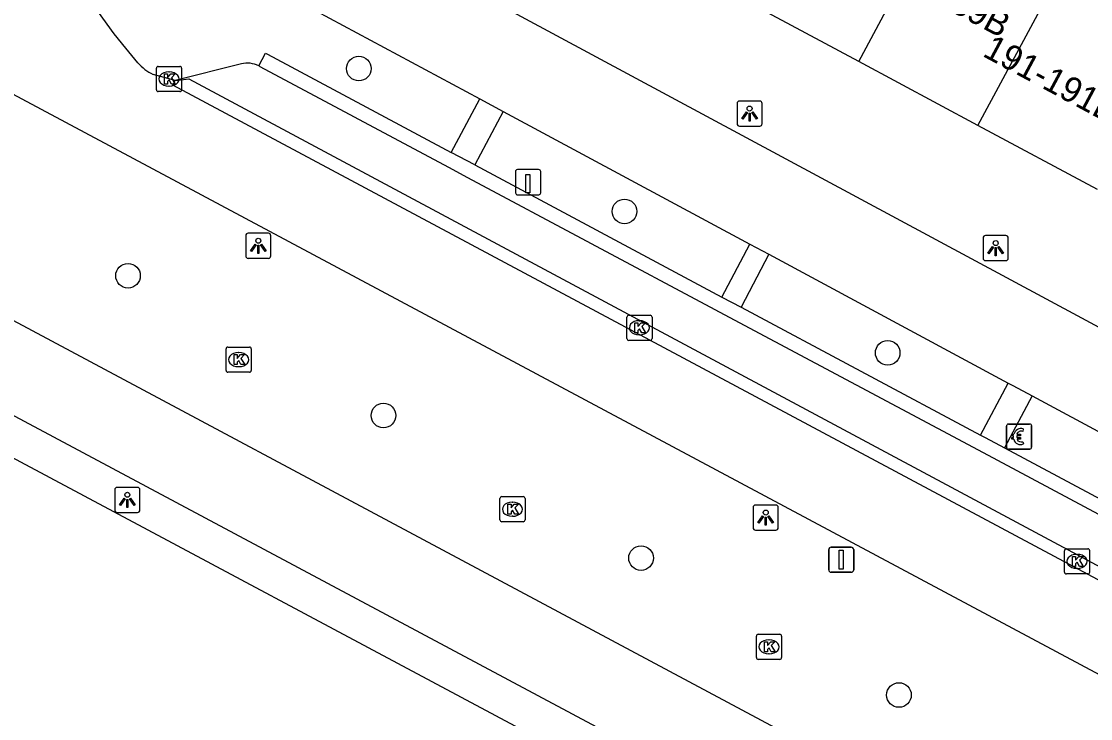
# Model space of a CAD drawing. Extents: x 159489 to 160304, y 383826 to 384530.
# Drawn here: x 159726.37 to 159768.87, y 384018.26 to 384045.99 of the extents above; entities that cross this region are included whole.
import ezdxf

# ---------------------------------------------------------------- set-up
doc = ezdxf.new("R2010")
doc.units = 0
for name, color, linetype in [('IMGEO_Betaalautomaat', 7, 'Continuous'), ('IMGEO_Boom', 7, 'Continuous'), ('IMGEO_Fietspad_gesloten', 7, 'Continuous'), ('IMGEO_Kolk', 7, 'Continuous'), ('IMGEO_Laadpaal', 7, 'Continuous'), ('IMGEO_Lichtpunt', 7, 'Continuous'), ('IMGEO_OVBaan_gesloten', 7, 'Continuous'), ('IMGEO_Pand', 7, 'Continuous'), ('IMGEO_Pand_nummerreeks', 7, 'Continuous'), ('IMGEO_Parkeervlak_open', 7, 'Continuous'), ('IMGEO_Rijbaan_lokaal_gesloten', 7, 'Continuous'), ('IMGEO_Rijbaan_lokaal_open', 7, 'Continuous'), ('IMGEO_Verkeersbordpaal', 7, 'Continuous'), ('IMGEO_Voetpad_open', 7, 'Continuous')]:
    doc.layers.add(name, color=color, linetype=linetype)

msp = doc.modelspace()

# ---------------------------------------------------------------- linework, layer by layer
at = {"layer": 'IMGEO_Betaalautomaat'}
for p, q in [((159765.601, 384029.975), (159766.442, 384029.975)), ((159766.442, 384029.975), (159765.601, 384029.975)), ((159765.526, 384029.051), (159765.526, 384029.892)), ((159765.526, 384029.892), (159765.526, 384029.051)), ((159765.809, 384029.439), (159765.809, 384029.507)), ((159765.93, 384029.507), (159765.93, 384029.439)), ((159766.188, 384029.78), (159766.171, 384029.68)), ((159766.525, 384029.901), (159766.525, 384029.06)), ((159766.525, 384029.06), (159766.525, 384029.901)), ((159766.175, 384029.274), (159766.197, 384029.187)), ((159766.451, 384028.976), (159765.61, 384028.976)), ((159765.61, 384028.976), (159766.451, 384028.976))]:
    msp.add_line(p, q, dxfattribs=at)
for points in [[(159765.809, 384029.507), (159765.74, 384029.507), (159765.74, 384029.576), (159765.819, 384029.576)], [(159765.941, 384029.576), (159766.088, 384029.576), (159766.088, 384029.507), (159765.93, 384029.507)], [(159765.814, 384029.37), (159765.74, 384029.37), (159765.74, 384029.439), (159765.809, 384029.439)], [(159765.93, 384029.439), (159766.088, 384029.439), (159766.088, 384029.37), (159765.944, 384029.37)]]:
    msp.add_lwpolyline(points, dxfattribs=at)
for centre, radius, start, end in [((159765.604, 384029.898), 0.0779, 92.4484, 184.2845), ((159765.604, 384029.898), 0.0779, 92.4484, 184.2845), ((159766.448, 384029.898), 0.0779, 2.4484, 94.2845), ((159766.448, 384029.898), 0.0779, 2.4484, 94.2845), ((159766.102, 384029.5), 0.293, 73.014, 165.0139), ((159766.108, 384029.513), 0.179, 69.3236, 159.5683), ((159766.075, 384029.425), 0.267, 191.8096, 297.0389), ((159766.108, 384029.44), 0.179, 202.7625, 291.8693), ((159765.604, 384029.054), 0.0779, 182.4484, 274.2845), ((159765.604, 384029.054), 0.0779, 182.4484, 274.2845), ((159766.448, 384029.054), 0.0779, 272.4484, 4.2845), ((159766.448, 384029.054), 0.0779, 272.4484, 4.2845)]:
    msp.add_arc(centre, radius, start, end, dxfattribs=at)
at = {"layer": 'IMGEO_Boom'}
for centre in [(159739.784, 384044.112), (159750.343, 384038.433), (159730.609, 384035.874), (159760.803, 384032.807), (159740.762, 384030.315), (159751, 384024.645), (159761.251, 384019.198)]:
    msp.add_circle(centre, 0.489, dxfattribs=at)
at = {"layer": 'IMGEO_Fietspad_gesloten'}
for points in [[(159797.098, 384018.803), (159731.166, 384054.292)], [(159729.77, 384050.977), (159731.079, 384050.354), (159731.013, 384050.208), (159744.588, 384042.906)], [(159744.588, 384042.906), (159745.526, 384042.402)], [(159745.526, 384042.402), (159755.319, 384037.135)], [(159755.319, 384037.135), (159756.08, 384036.725)], [(159756.08, 384036.725), (159765.597, 384031.607)], [(159765.597, 384031.607), (159765.779, 384031.509), (159766.543, 384031.098)], [(159766.543, 384031.098), (159776.103, 384025.957), (159776.158, 384025.928)]]:
    msp.add_lwpolyline(points, dxfattribs=at)
at = {"layer": 'IMGEO_Kolk'}
for p, q in [((159731.739, 384043.272), (159731.739, 384044.124)), ((159731.814, 384044.198), (159732.666, 384044.198)), ((159732.227, 384043.978), (159732.252, 384043.978)), ((159732.74, 384044.124), (159732.74, 384043.272)), ((159732.666, 384043.198), (159731.814, 384043.198)), ((159732.25, 384043.418), (159732.225, 384043.418)), ((159750.435, 384033.378), (159750.435, 384034.23)), ((159750.51, 384034.304), (159751.362, 384034.304)), ((159751.436, 384034.23), (159751.436, 384033.378)), ((159750.923, 384034.084), (159750.948, 384034.084)), ((159750.946, 384033.524), (159750.921, 384033.524)), ((159734.506, 384032.111), (159734.506, 384032.963)), ((159734.581, 384033.037), (159735.433, 384033.037)), ((159735.507, 384032.963), (159735.507, 384032.111)), ((159751.362, 384033.304), (159750.51, 384033.304)), ((159734.994, 384032.817), (159735.019, 384032.817)), ((159735.017, 384032.257), (159734.992, 384032.257)), ((159735.433, 384032.037), (159734.581, 384032.037)), ((159745.388, 384026.162), (159745.388, 384027.014)), ((159745.463, 384027.088), (159746.315, 384027.088)), ((159746.389, 384027.014), (159746.389, 384026.162)), ((159745.876, 384026.868), (159745.901, 384026.868)), ((159745.899, 384026.308), (159745.874, 384026.308)), ((159746.315, 384026.088), (159745.463, 384026.088)), ((159767.83, 384024.087), (159767.83, 384024.939)), ((159767.905, 384025.013), (159768.757, 384025.013)), ((159768.831, 384024.939), (159768.831, 384024.087)), ((159768.318, 384024.793), (159768.343, 384024.793)), ((159768.757, 384024.013), (159767.905, 384024.013)), ((159768.341, 384024.233), (159768.316, 384024.233)), ((159755.585, 384020.689), (159755.585, 384021.541)), ((159755.66, 384021.615), (159756.512, 384021.615)), ((159756.586, 384021.541), (159756.586, 384020.689)), ((159756.073, 384021.395), (159756.098, 384021.395)), ((159756.512, 384020.615), (159755.66, 384020.615)), ((159756.096, 384020.835), (159756.071, 384020.835))]:
    msp.add_line(p, q, dxfattribs=at)
for points in [[(159731.739, 384043.272), (159731.739, 384044.124)], [(159731.814, 384044.198), (159732.666, 384044.198)], [(159732.74, 384044.124), (159732.74, 384043.272)], [(159732.06, 384043.898), (159732.183, 384043.898), (159732.183, 384043.747), (159732.313, 384043.898), (159732.477, 384043.898), (159732.331, 384043.747), (159732.484, 384043.498), (159732.332, 384043.498), (159732.247, 384043.662), (159732.183, 384043.595), (159732.183, 384043.498), (159732.06, 384043.498), (159732.06, 384043.898)], [(159732.666, 384043.198), (159731.814, 384043.198)], [(159750.435, 384033.378), (159750.435, 384034.23)], [(159750.51, 384034.304), (159751.362, 384034.304)], [(159751.436, 384034.23), (159751.436, 384033.378)], [(159750.756, 384034.004), (159750.879, 384034.004), (159750.879, 384033.853), (159751.009, 384034.004), (159751.173, 384034.004), (159751.027, 384033.853), (159751.18, 384033.604), (159751.028, 384033.604), (159750.943, 384033.768), (159750.879, 384033.701), (159750.879, 384033.604), (159750.756, 384033.604), (159750.756, 384034.004)], [(159734.506, 384032.111), (159734.506, 384032.963)], [(159734.581, 384033.037), (159735.433, 384033.037)], [(159735.507, 384032.963), (159735.507, 384032.111)], [(159751.362, 384033.304), (159750.51, 384033.304)], [(159734.827, 384032.737), (159734.95, 384032.737), (159734.95, 384032.586), (159735.08, 384032.737), (159735.244, 384032.737), (159735.098, 384032.586), (159735.251, 384032.337), (159735.099, 384032.337), (159735.014, 384032.501), (159734.95, 384032.434), (159734.95, 384032.337), (159734.827, 384032.337), (159734.827, 384032.737)], [(159735.433, 384032.037), (159734.581, 384032.037)], [(159745.388, 384026.162), (159745.388, 384027.014)], [(159745.463, 384027.088), (159746.315, 384027.088)], [(159746.389, 384027.014), (159746.389, 384026.162)], [(159745.709, 384026.788), (159745.832, 384026.788), (159745.832, 384026.637), (159745.962, 384026.788), (159746.126, 384026.788), (159745.98, 384026.637), (159746.133, 384026.388), (159745.981, 384026.388), (159745.896, 384026.552), (159745.832, 384026.485), (159745.832, 384026.388), (159745.709, 384026.388), (159745.709, 384026.788)], [(159746.315, 384026.088), (159745.463, 384026.088)], [(159767.83, 384024.087), (159767.83, 384024.939)], [(159767.905, 384025.013), (159768.757, 384025.013)], [(159768.831, 384024.939), (159768.831, 384024.087)], [(159768.151, 384024.713), (159768.274, 384024.713), (159768.274, 384024.562), (159768.404, 384024.713), (159768.568, 384024.713), (159768.422, 384024.562), (159768.575, 384024.313), (159768.423, 384024.313), (159768.338, 384024.477), (159768.274, 384024.41), (159768.274, 384024.313), (159768.151, 384024.313), (159768.151, 384024.713)], [(159768.757, 384024.013), (159767.905, 384024.013)], [(159755.585, 384020.689), (159755.585, 384021.541)], [(159755.66, 384021.615), (159756.512, 384021.615)], [(159756.586, 384021.541), (159756.586, 384020.689)], [(159755.906, 384021.315), (159756.029, 384021.315), (159756.029, 384021.164), (159756.159, 384021.315), (159756.323, 384021.315), (159756.177, 384021.164), (159756.33, 384020.915), (159756.178, 384020.915), (159756.093, 384021.079), (159756.029, 384021.012), (159756.029, 384020.915), (159755.906, 384020.915), (159755.906, 384021.315)], [(159756.512, 384020.615), (159755.66, 384020.615)]]:
    msp.add_lwpolyline(points, dxfattribs=at)
for centre, start, end in [((159731.816, 384044.122), 91.552, 178.448), ((159731.816, 384044.122), 91.552, 178.448), ((159732.664, 384044.122), 1.552, 88.448), ((159732.664, 384044.122), 1.552, 88.448), ((159731.816, 384043.274), 181.552, 268.448), ((159731.816, 384043.274), 181.552, 268.448), ((159732.664, 384043.274), 271.552, 358.448), ((159732.664, 384043.274), 271.552, 358.448), ((159750.512, 384034.228), 91.552, 178.448), ((159750.512, 384034.228), 91.552, 178.448), ((159751.36, 384034.228), 1.552, 88.448), ((159751.36, 384034.228), 1.552, 88.448), ((159750.512, 384033.38), 181.552, 268.448), ((159750.512, 384033.38), 181.552, 268.448), ((159751.36, 384033.38), 271.552, 358.448), ((159751.36, 384033.38), 271.552, 358.448), ((159734.583, 384032.961), 91.552, 178.448), ((159734.583, 384032.961), 91.552, 178.448), ((159735.431, 384032.961), 1.552, 88.448), ((159735.431, 384032.961), 1.552, 88.448), ((159734.583, 384032.113), 181.552, 268.448), ((159734.583, 384032.113), 181.552, 268.448), ((159735.431, 384032.113), 271.552, 358.448), ((159735.431, 384032.113), 271.552, 358.448), ((159745.465, 384027.012), 91.552, 178.448), ((159745.465, 384027.012), 91.552, 178.448), ((159746.313, 384027.012), 1.552, 88.448), ((159746.313, 384027.012), 1.552, 88.448), ((159745.465, 384026.164), 181.552, 268.448), ((159745.465, 384026.164), 181.552, 268.448), ((159746.313, 384026.164), 271.552, 358.448), ((159746.313, 384026.164), 271.552, 358.448), ((159767.907, 384024.937), 91.552, 178.448), ((159767.907, 384024.937), 91.552, 178.448), ((159768.755, 384024.937), 1.552, 88.448), ((159768.755, 384024.937), 1.552, 88.448), ((159767.907, 384024.089), 181.552, 268.448), ((159767.907, 384024.089), 181.552, 268.448), ((159768.755, 384024.089), 271.552, 358.448), ((159768.755, 384024.089), 271.552, 358.448), ((159755.662, 384021.539), 91.552, 178.448), ((159755.662, 384021.539), 91.552, 178.448), ((159756.51, 384021.539), 1.552, 88.448), ((159756.51, 384021.539), 1.552, 88.448), ((159755.662, 384020.691), 181.552, 268.448), ((159755.662, 384020.691), 181.552, 268.448), ((159756.51, 384020.691), 271.552, 358.448), ((159756.51, 384020.691), 271.552, 358.448)]:
    msp.add_arc(centre, 0.0765, start, end, dxfattribs=at)
for centre, major_axis, ratio, start_param, end_param in [((159732.226, 384043.698), (-0.387, 0.002), 0.722429, 4.712389, 7.853982), ((159732.251, 384043.698), (-0.39, 0.002), 0.717154, 1.570796, 4.712389), ((159750.922, 384033.804), (-0.387, 0.002), 0.722429, 4.712389, 7.853982), ((159750.947, 384033.804), (-0.39, 0.002), 0.717154, 1.570796, 4.712389), ((159734.993, 384032.537), (-0.387, 0.002), 0.722429, 4.712389, 7.853982), ((159735.018, 384032.537), (-0.39, 0.002), 0.717154, 1.570796, 4.712389), ((159745.875, 384026.588), (-0.387, 0.002), 0.722429, 4.712389, 7.853982), ((159745.9, 384026.588), (-0.39, 0.002), 0.717154, 1.570796, 4.712389), ((159768.317, 384024.513), (-0.387, 0.002), 0.722429, 4.712389, 7.853982), ((159768.342, 384024.513), (-0.39, 0.002), 0.717154, 1.570796, 4.712389), ((159756.072, 384021.115), (-0.387, 0.002), 0.722429, 4.712389, 7.853982), ((159756.097, 384021.115), (-0.39, 0.002), 0.717154, 1.570796, 4.712389)]:
    msp.add_ellipse(centre, major_axis=major_axis, ratio=ratio, start_param=start_param, end_param=end_param, dxfattribs=at)
at = {"layer": 'IMGEO_Laadpaal'}
for p, q in [((159746.011, 384040.009), (159746.011, 384039.168)), ((159746.011, 384040.009), (159746.011, 384039.168)), ((159746.927, 384040.093), (159746.086, 384040.093)), ((159746.927, 384040.093), (159746.086, 384040.093)), ((159747.011, 384039.177), (159747.011, 384040.018)), ((159747.011, 384039.177), (159747.011, 384040.018)), ((159746.095, 384039.093), (159746.936, 384039.093)), ((159746.095, 384039.093), (159746.936, 384039.093))]:
    msp.add_line(p, q, dxfattribs=at)
msp.add_lwpolyline([(159746.426, 384039.906), (159746.586, 384039.906), (159746.586, 384039.173), (159746.426, 384039.173), (159746.426, 384039.906)], dxfattribs=at)
for centre, start, end in [((159746.089, 384040.015), 92.4484, 184.2845), ((159746.089, 384040.015), 92.4484, 184.2845), ((159746.933, 384040.015), 2.4484, 94.2845), ((159746.933, 384040.015), 2.4484, 94.2845), ((159746.089, 384039.171), 182.4484, 274.2845), ((159746.089, 384039.171), 182.4484, 274.2845), ((159746.933, 384039.171), 272.4484, 4.2845), ((159746.933, 384039.171), 272.4484, 4.2845)]:
    msp.add_arc(centre, 0.0779, start, end, dxfattribs=at)
at = {"layer": 'IMGEO_Lichtpunt'}
for p, q in [((159754.817, 384042.726), (159754.817, 384041.919)), ((159754.817, 384042.726), (159754.817, 384041.919)), ((159755.719, 384042.821), (159754.911, 384042.821)), ((159755.719, 384042.821), (159754.911, 384042.821)), ((159755.813, 384041.919), (159755.813, 384042.726)), ((159755.813, 384041.919), (159755.813, 384042.726)), ((159754.911, 384041.825), (159755.719, 384041.825)), ((159754.911, 384041.825), (159755.719, 384041.825)), ((159735.289, 384037.467), (159735.289, 384036.66)), ((159735.289, 384037.467), (159735.289, 384036.66)), ((159736.191, 384037.562), (159735.383, 384037.562)), ((159736.191, 384037.562), (159735.383, 384037.562)), ((159736.285, 384036.66), (159736.285, 384037.467)), ((159736.285, 384036.66), (159736.285, 384037.467)), ((159764.597, 384037.376), (159764.597, 384036.569)), ((159764.597, 384037.376), (159764.597, 384036.569)), ((159765.499, 384037.471), (159764.691, 384037.471)), ((159765.499, 384037.471), (159764.691, 384037.471)), ((159765.593, 384036.569), (159765.593, 384037.376)), ((159765.593, 384036.569), (159765.593, 384037.376)), ((159735.383, 384036.566), (159736.191, 384036.566)), ((159735.383, 384036.566), (159736.191, 384036.566)), ((159764.691, 384036.475), (159765.499, 384036.475)), ((159764.691, 384036.475), (159765.499, 384036.475)), ((159730.986, 384027.457), (159730.178, 384027.457)), ((159730.986, 384027.457), (159730.178, 384027.457)), ((159730.084, 384027.362), (159730.084, 384026.555)), ((159730.084, 384027.362), (159730.084, 384026.555)), ((159731.08, 384026.555), (159731.08, 384027.362)), ((159731.08, 384026.555), (159731.08, 384027.362)), ((159755.456, 384026.658), (159755.456, 384025.851)), ((159755.456, 384026.658), (159755.456, 384025.851)), ((159756.358, 384026.753), (159755.55, 384026.753)), ((159756.358, 384026.753), (159755.55, 384026.753)), ((159756.452, 384025.851), (159756.452, 384026.658)), ((159756.452, 384025.851), (159756.452, 384026.658)), ((159730.178, 384026.461), (159730.986, 384026.461)), ((159730.178, 384026.461), (159730.986, 384026.461)), ((159755.55, 384025.757), (159756.358, 384025.757)), ((159755.55, 384025.757), (159756.358, 384025.757))]:
    msp.add_line(p, q, dxfattribs=at)
for points in [[(159755.191, 384042.39), (159755.23, 384042.362), (159755.042, 384042.1), (159755.004, 384042.127), (159755.191, 384042.39)], [(159755.293, 384042.342), (159755.34, 384042.342), (159755.34, 384042.02), (159755.293, 384042.02), (159755.293, 384042.342)], [(159755.403, 384042.362), (159755.441, 384042.389), (159755.628, 384042.127), (159755.589, 384042.099), (159755.403, 384042.362)], [(159735.663, 384037.131), (159735.702, 384037.103), (159735.514, 384036.841), (159735.476, 384036.868), (159735.663, 384037.131)], [(159735.765, 384037.083), (159735.812, 384037.083), (159735.812, 384036.761), (159735.765, 384036.761), (159735.765, 384037.083)], [(159735.875, 384037.103), (159735.913, 384037.13), (159736.1, 384036.868), (159736.061, 384036.84), (159735.875, 384037.103)], [(159764.971, 384037.04), (159765.01, 384037.012), (159764.822, 384036.75), (159764.784, 384036.777), (159764.971, 384037.04)], [(159765.073, 384036.992), (159765.12, 384036.992), (159765.12, 384036.67), (159765.073, 384036.67), (159765.073, 384036.992)], [(159765.183, 384037.012), (159765.221, 384037.039), (159765.408, 384036.777), (159765.369, 384036.749), (159765.183, 384037.012)], [(159730.458, 384027.026), (159730.497, 384026.998), (159730.309, 384026.736), (159730.271, 384026.763), (159730.458, 384027.026)], [(159730.56, 384026.978), (159730.607, 384026.978), (159730.607, 384026.656), (159730.56, 384026.656), (159730.56, 384026.978)], [(159730.67, 384026.998), (159730.708, 384027.025), (159730.895, 384026.763), (159730.856, 384026.735), (159730.67, 384026.998)], [(159755.83, 384026.322), (159755.869, 384026.294), (159755.681, 384026.032), (159755.643, 384026.059), (159755.83, 384026.322)], [(159755.932, 384026.274), (159755.979, 384026.274), (159755.979, 384025.952), (159755.932, 384025.952), (159755.932, 384026.274)], [(159756.042, 384026.294), (159756.08, 384026.321), (159756.267, 384026.059), (159756.228, 384026.031), (159756.042, 384026.294)]]:
    msp.add_lwpolyline(points, dxfattribs=at)
for centre in [(159755.316, 384042.524), (159735.788, 384037.265), (159765.096, 384037.174), (159730.583, 384027.16), (159755.955, 384026.456)]:
    msp.add_circle(centre, 0.0994, dxfattribs=at)
for centre, start, end in [((159754.911, 384042.726), 90, 180), ((159754.911, 384042.726), 90, 180), ((159755.719, 384042.726), 0, 90), ((159755.719, 384042.726), 0, 90), ((159754.911, 384041.919), 180, 270), ((159754.911, 384041.919), 180, 270), ((159755.719, 384041.919), 270, 0), ((159755.719, 384041.919), 270, 360), ((159735.383, 384037.467), 90, 180), ((159735.383, 384037.467), 90, 180), ((159736.191, 384037.467), 0, 90), ((159736.191, 384037.467), 0, 90), ((159764.691, 384037.376), 90, 180), ((159764.691, 384037.376), 90, 180), ((159765.499, 384037.376), 0, 90), ((159765.499, 384037.376), 0, 90), ((159735.383, 384036.66), 180, 270), ((159735.383, 384036.66), 180, 270), ((159736.191, 384036.66), 270, 0), ((159736.191, 384036.66), 270, 360), ((159764.691, 384036.569), 180, 270), ((159764.691, 384036.569), 180, 270), ((159765.499, 384036.569), 270, 0), ((159765.499, 384036.569), 270, 360), ((159730.178, 384027.362), 90, 180), ((159730.178, 384027.362), 90, 180), ((159730.986, 384027.362), 0, 90), ((159730.986, 384027.362), 0, 90), ((159730.178, 384026.555), 180, 270), ((159730.178, 384026.555), 180, 270), ((159730.986, 384026.555), 270, 0), ((159730.986, 384026.555), 270, 360), ((159755.55, 384026.658), 90, 180), ((159755.55, 384026.658), 90, 180), ((159756.358, 384026.658), 0, 90), ((159756.358, 384026.658), 0, 90), ((159755.55, 384025.851), 180, 270), ((159755.55, 384025.851), 180, 270), ((159756.358, 384025.851), 270, 0), ((159756.358, 384025.851), 270, 360)]:
    msp.add_arc(centre, 0.0946, start, end, dxfattribs=at)
at = {"layer": 'IMGEO_OVBaan_gesloten'}
for points in [[(159778.419, 384002.326), (159655.116, 384068.233), (159654.047, 384068.903), (159653.178, 384069.297)], [(159777.482, 384006.579), (159693.976, 384051.25)]]:
    msp.add_lwpolyline(points, dxfattribs=at)
at = {"layer": 'IMGEO_Pand'}
for points in [[(159759.654, 384044.398), (159765.389, 384055.118), (159766.267, 384056.759)], [(159764.388, 384041.852), (159770.147, 384052.559), (159771.029, 384054.198)], [(159759.654, 384044.398), (159754.877, 384046.966)], [(159764.388, 384041.852), (159759.654, 384044.398)], [(159769.137, 384039.299), (159764.388, 384041.852)]]:
    msp.add_lwpolyline(points, dxfattribs=at)
at = {"layer": 'IMGEO_Parkeervlak_open'}
msp.add_lwpolyline([(159735.114, 384044.297), (159732.479, 384043.633)], dxfattribs=at)
msp.add_arc((159735.358, 384043.377), 0.951, 62.0804, 104.8377, dxfattribs=at)
at = {"layer": 'IMGEO_Rijbaan_lokaal_gesloten'}
for points in [[(159651.039, 384068.82), (159654.602, 384066.798), (159694.996, 384045.215), (159777.713, 384001.02)], [(159731.001, 384044.339), (159730.518, 384044.924), (159730.06, 384045.499), (159729.441, 384046.354)], [(159722.71, 384044.871), (159782.754, 384012.782)], [(159732.479, 384043.633), (159731.607, 384043.881)], [(159784.967, 384015.376), (159784.85, 384015.386), (159732.397, 384043.459), (159732.479, 384043.633)]]:
    msp.add_lwpolyline(points, dxfattribs=at)
msp.add_arc((159732.536, 384045.74), 2.078, 222.3887, 243.4491, dxfattribs=at)
at = {"layer": 'IMGEO_Rijbaan_lokaal_open'}
msp.add_lwpolyline([(159732.479, 384043.633), (159733.023, 384043.708), (159783.959, 384016.413), (159783.95, 384016.527)], dxfattribs=at)
at = {"layer": 'IMGEO_Verkeersbordpaal'}
for p, q in [((159758.461, 384024.179), (159758.461, 384024.979)), ((159758.461, 384024.979), (159758.461, 384024.179)), ((159758.561, 384025.079), (159759.351, 384025.079)), ((159759.351, 384025.079), (159758.561, 384025.079)), ((159759.451, 384024.979), (159759.451, 384024.179)), ((159759.451, 384024.179), (159759.451, 384024.979)), ((159759.351, 384024.079), (159758.561, 384024.079)), ((159758.561, 384024.079), (159759.351, 384024.079))]:
    msp.add_line(p, q, dxfattribs=at)
msp.add_lwpolyline([(159758.881, 384024.954), (159759.031, 384024.954), (159759.031, 384024.204), (159758.881, 384024.204), (159758.881, 384024.954)], dxfattribs=at)
for centre, start, end in [((159758.561, 384024.979), 90, 180), ((159758.561, 384024.979), 90, 180), ((159759.351, 384024.979), 0, 90), ((159759.351, 384024.979), 360, 90), ((159758.561, 384024.179), 180, 270), ((159758.561, 384024.179), 180, 270), ((159759.351, 384024.179), 270, 0), ((159759.351, 384024.179), 270, 0)]:
    msp.add_arc(centre, 0.1, start, end, dxfattribs=at)
at = {"layer": 'IMGEO_Voetpad_open'}
for points in [[(159735.803, 384044.218), (159736.071, 384044.724), (159736.097, 384044.71), (159736.122, 384044.696), (159736.147, 384044.681), (159743.451, 384040.779)], [(159782.699, 384019.159), (159775.691, 384022.903), (159774.939, 384023.305), (159765.175, 384028.522), (159764.408, 384028.932), (159754.714, 384034.111), (159753.949, 384034.52), (159744.117, 384039.773), (159743.356, 384040.18), (159735.862, 384044.184)], [(159743.451, 384040.779), (159744.588, 384042.906)], [(159745.526, 384042.402), (159744.388, 384040.278)], [(159744.388, 384040.278), (159743.451, 384040.779)], [(159744.388, 384040.278), (159754.215, 384035.027)], [(159754.215, 384035.027), (159755.319, 384037.135)], [(159756.08, 384036.725), (159754.979, 384034.619)], [(159754.215, 384035.027), (159754.979, 384034.619)], [(159754.979, 384034.619), (159764.491, 384029.537)], [(159764.491, 384029.537), (159765.597, 384031.607)], [(159766.543, 384031.098), (159765.444, 384029.028)], [(159764.491, 384029.537), (159764.677, 384029.438), (159765.444, 384029.028)], [(159765.444, 384029.028), (159775.012, 384023.915), (159775.067, 384023.886)]]:
    msp.add_lwpolyline(points, dxfattribs=at)
msp.add_arc((159735.573, 384043.752), 0.52, 56.2914, 63.8014, dxfattribs=at)

# ---------------------------------------------------------------- texts
at = {"layer": 'IMGEO_Pand_nummerreeks'}
for s, rotation, p in [('189-189B', 331.6902, (159760.209, 384048.062)), ('191-191B', 331.7818, (159764.533, 384044.627))]:
    msp.add_text(s, height=1, rotation=rotation, dxfattribs=at).set_placement(p)

doc.saveas('drawing.dxf')
